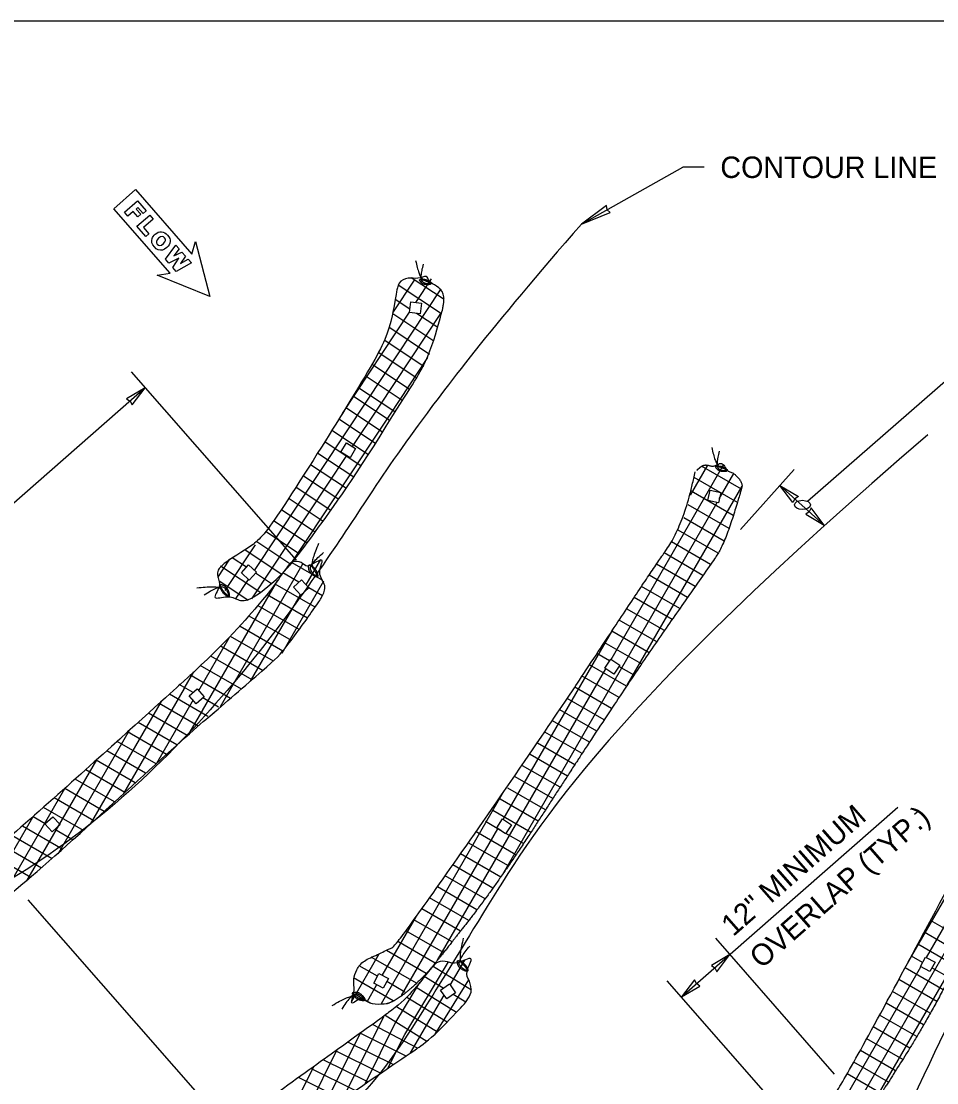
# Model space of a CAD drawing. Extents: x 99862 to 103680, y 99470 to 102076.
# Drawn here: x 100410 to 101092, y 101285 to 102076 of the extents above; entities that cross this region are included whole.
import ezdxf

# ---------------------------------------------------------------- set-up
doc = ezdxf.new("R2010")
doc.units = 0
for name, color, linetype in [('Level 1', 7, 'Continuous'), ('Level 10', 7, 'Continuous'), ('Level 15', 7, 'Continuous'), ('Level 20', 7, 'Continuous'), ('Level 4', 7, 'Continuous'), ('Level 9', 7, 'Continuous')]:
    doc.layers.add(name, color=color, linetype=linetype)

msp = doc.modelspace()

# ---------------------------------------------------------------- linework, layer by layer
at = {"layer": 'Level 1'}
msp.add_lwpolyline([(99862, 99999.5), (103151, 99999.5), (103151, 102075.5), (99862, 102075.5)], close=True, dxfattribs=at)
at = {"layer": 'Level 10'}
for p, q in [((100686.69, 101781.75), (100686.69, 101781.75)), ((100528.6, 101581.63), (100528.6, 101581.63)), ((100550.56, 101557.94), (100550.6, 101557.88)), ((100550.6, 101557.88), (100553.54, 101560.47))]:
    msp.add_line(p, q, dxfattribs=at)
for points, degree in [([(100703.82, 101897.11), (100706.88, 101883.28), (100711.8, 101883.38), (100716.73, 101879.3), (100709.52, 101879.05), (100707.92, 101880.94)], 2), ([(100707.92, 101880.94), (100706.18, 101882.83), (100708.14, 101883.42), (100715.85, 101880.26), (100711.97, 101879.45), (100706.5, 101882.66), (100709.63, 101894.37)], 2), ([(100686.69, 101781.75), (100703.73, 101807.89), (100713.64, 101823.92), (100724, 101860.58), (100724.42, 101863.23), (100725.56, 101872.86), (100719.55, 101878.66), (100713.08, 101881.07), (100712.79, 101887.05), (100705.43, 101882.88), (100698.53, 101885.09), (100692.9, 101882.35), (100691.65, 101880.34)], 3), ([(100691.65, 101880.34), (100690.4, 101878.32), (100689.61, 101874.46), (100683.89, 101838.84), (100667.45, 101813.31), (100649.17, 101783.11)], 3), ([(100649.17, 101783.11), (100643.46, 101773.88), (100595.75, 101697.56), (100583.93, 101685.4), (100556.89, 101669.91), (100555.08, 101662.87), (100559.51, 101654.84), (100550.53, 101643.35), (100564.54, 101648.13), (100570.49, 101644.09), (100580.38, 101642.5), (100606.82, 101665.1), (100621.99, 101685.13), (100660.69, 101738.67), (100686.69, 101781.75)], 3), ([(100924.56, 101757.81), (100927.68, 101743.99), (100932.6, 101744.13), (100937.55, 101740.07), (100930.34, 101739.78), (100928.74, 101741.66)], 2), ([(100928.74, 101741.66), (100926.99, 101743.55), (100928.95, 101744.14), (100936.66, 101741.02), (100932.79, 101740.19), (100927.31, 101743.38), (100930.37, 101755.1)], 2), ([(100913.39, 101740.65), (100915.97, 101743.47), (100919.92, 101745.31), (100926.13, 101743.35), (100932.33, 101747.32), (100936.21, 101739.99), (100941.25, 101738.92), (100948.01, 101730.88), (100945.85, 101724.48), (100945.34, 101721.84), (100933.71, 101685.57), (100922.62, 101668.96), (100878.53, 101606.33), (100829.81, 101533.12), (100767.38, 101436.3), (100724.87, 101381.61), (100709.01, 101362.12), (100686.58, 101343.34), (100671.98, 101342.39), (100662.3, 101348.01), (100654.75, 101341.78), (100658.72, 101354.02), (100656.73, 101360.34), (100662.32, 101375.12), (100684.12, 101383.21), (100693.17, 101391.91), (100793.37, 101535.2), (100878.11, 101663.54), (100904.5, 101701.51), (100912.19, 101739.82)], 2), ([(100631.4, 101686.31), (100624.74, 101670.67), (100629.62, 101667.34), (100631.58, 101659.91), (100624.37, 101664.7), (100624.13, 101667.65)], 2), ([(100624.13, 101667.65), (100623.75, 101670.72), (100626.07, 101669.92), (100631.39, 101661.46), (100627.04, 101663.38), (100623.94, 101670.32), (100635.16, 101679.58)], 2), ([(100611.16, 101672.08), (100609.65, 101671.07), (100605.18, 101665.16), (100592.45, 101646.1), (100558.31, 101608.42), (100528.6, 101581.63)], 3), ([(100550.6, 101557.88), (100559.43, 101565.55), (100597.07, 101597.71), (100605.65, 101606.27), (100632.18, 101643.31), (100633.34, 101645.74), (100638.42, 101655.09), (100629.46, 101663.66), (100637.37, 101677.27), (100625.16, 101669.8), (100622.44, 101668.85), (100617.18, 101673.65), (100612.67, 101673.09), (100611.16, 101672.08)], 3), ([(101201.98, 101650.48), (101204.23, 101654.65), (101209.68, 101657.73), (101216.7, 101655.95), (101223.8, 101660.57), (101224.45, 101654.62), (101231.06, 101652.6), (101237.42, 101647.19), (101236.87, 101637.51), (101236.61, 101634.83), (101228.53, 101597.61), (101219.1, 101580.01), (101181.24, 101513.43), (101139.8, 101435.86), (101086.99, 101333.49), (101049.94, 101274.95), (101036.04, 101254.03), (101011.04, 101229.85), (101001.08, 101230.82), (100994.88, 101234.48), (100983.57, 101230.11), (100989.45, 101240.88), (100984.53, 101248.61), (100985.9, 101255.76), (101011.94, 101272.88), (101018.02, 101275.83), (101103.33, 101434.43), (101175.32, 101570.33), (101197.92, 101610.67), (101201.44, 101646.58)], 2), ([(100528.6, 101581.63), (100528.11, 101581.18), (100470.66, 101529.07), (100345.88, 101417.9), (100320.67, 101410.22), (100299.49, 101400.95), (100293.76, 101394.13), (100297.49, 101385.18), (100287.56, 101376.44), (100301.23, 101377.9), (100305.39, 101373.25), (100317.46, 101371.44), (100346.05, 101382.29), (100366.25, 101397.24), (100420.98, 101439.69), (100505.45, 101518.02), (100543.69, 101552.46), (100550.6, 101557.88)], 3), ([(100720.66, 101374.47), (100718.94, 101373.7), (100717, 101372.6), (100697.09, 101346.06), (100683.68, 101336.84)], 3), ([(100704.56, 101309.85), (100704.78, 101309.98), (100713.59, 101315.17), (100739.82, 101342.78), (100741.44, 101344.93), (100746.22, 101351.69), (100744.31, 101360.85), (100739.79, 101366.11), (100749.24, 101380.94), (100733.21, 101371.83), (100728.29, 101375.07), (100722.37, 101375.24), (100720.66, 101374.47)], 3), ([(100683.65, 101336.86), (100679.43, 101333.35), (100655.62, 101316.88), (100531.24, 101226.43), (100387.02, 101132.84), (100378.6, 101128.6), (100349.84, 101116.39), (100347.55, 101104.92), (100340.78, 101099.98), (100337.73, 101096.69), (100347.02, 101095.39), (100349.87, 101092.19), (100366.06, 101083.31), (100391.52, 101093.94), (100413.21, 101106.63), (100472.21, 101142.93), (100564.63, 101211.69), (100635.94, 101263.16), (100694, 101302.8), (100704.56, 101309.85)], 3)]:
    msp.add_open_spline(points, degree=degree, dxfattribs=at)
at = {"layer": 'Level 15'}
for p, q in [((100827.57, 101924.36), (100903, 101966.69)), ((100919, 101966.69), (100903, 101966.69)), ((100995.89, 101717.8), (101136.22, 101840.29)), ((100491.66, 101814.31), (100614.68, 101673.96)), ((100502.21, 101802.28), (100177.84, 101517.98)), ((100946.01, 101696.71), (100986.06, 101741.52)), ((101008.42, 101700.01), (100975.37, 101729.56)), ((100901.95, 101348.47), (101063.39, 101489.97)), ((101075.63, 101484.69), (101077.71, 101486.32)), ((101016.17, 101290.98), (100927.5, 101392.14)), ((100987.79, 101250.53), (100891.4, 101360.5))]:
    msp.add_line(p, q, dxfattribs=at)
for points in [[(100827.57, 101924.36), (100848.94, 101932.93), (100846.56, 101935.02), (100846.02, 101938.14)], [(100502.21, 101802.28), (100488.37, 101794.2), (100490.96, 101792.37), (100492.45, 101789.57)], [(100975.37, 101729.56), (100989.15, 101721.38), (100986.55, 101719.57), (100985.04, 101716.78)], [(101008.42, 101700.01), (100998.76, 101712.79), (100997.24, 101710.01), (100994.65, 101708.19)], [(100938.06, 101380.05), (100924.29, 101371.85), (100926.89, 101370.04), (100928.4, 101367.26)], [(100901.95, 101348.47), (100915.79, 101356.55), (100913.21, 101358.38), (100911.71, 101361.18)]]:
    msp.add_lwpolyline(points, close=True, dxfattribs=at)
msp.add_ellipse((100992.2, 101715.06), major_axis=(-6, 0), ratio=0.57735, dxfattribs=at)
at = {"layer": 'Level 20'}
msp.add_line((100414.74, 101420.89), (100555.73, 101260.03), dxfattribs=at)
for points in [[(100550.26, 101870.27), (100511.05, 101886.39), (100520.73, 101887.65), (100478.73, 101935.81), (100495.06, 101950.06), (100537.06, 101901.89), (100539.63, 101911.32), (100550.26, 101870.27)], [(100550.26, 101870.27), (100511.05, 101886.39), (100520.73, 101887.65), (100478.73, 101935.81), (100495.06, 101950.06), (100537.06, 101901.89), (100539.63, 101911.32), (100550.26, 101870.27)], [(100496.38, 101941.58), (100502.83, 101934.18), (100500.61, 101932.25), (100496.74, 101936.68), (100495.44, 101935.55), (100498.83, 101931.67), (100496.61, 101929.74), (100493.23, 101933.62), (100489.34, 101930.23), (100486.77, 101933.19), (100496.38, 101941.58)], [(100496.38, 101941.58), (100502.83, 101934.18), (100500.61, 101932.25), (100496.74, 101936.68), (100495.44, 101935.55), (100498.83, 101931.67), (100496.61, 101929.74), (100493.23, 101933.62), (100489.34, 101930.23), (100486.77, 101933.19), (100496.38, 101941.58)], [(100505.54, 101931.07), (100508.12, 101928.11), (100500.91, 101921.82), (100504.95, 101917.2), (100502.54, 101915.1), (100495.93, 101922.68), (100505.54, 101931.07)], [(100505.54, 101931.07), (100508.12, 101928.11), (100500.91, 101921.82), (100504.95, 101917.2), (100502.54, 101915.1), (100495.93, 101922.68), (100505.54, 101931.07)], [(100518.91, 101916.11), (100519.82, 101914.91), (100520.45, 101913.7), (100520.79, 101912.49), (100520.85, 101911.28), (100520.63, 101910.09), (100520.15, 101908.94), (100519.39, 101907.85), (100518.36, 101906.81), (100516.69, 101905.61), (100515.09, 101904.96), (100513.52, 101904.81), (100511.97, 101905.13), (100510.47, 101905.95), (100509.03, 101907.29), (100507.86, 101908.89), (100507.2, 101910.44), (100507.02, 101911.99), (100507.34, 101913.6), (100507.68, 101914.42), (100508.17, 101915.21), (100508.8, 101915.98), (100509.58, 101916.73), (100510.76, 101917.62), (100511.96, 101918.23), (100513.17, 101918.57), (100514.4, 101918.62), (100515.6, 101918.41), (100516.76, 101917.91), (100517.86, 101917.15), (100518.91, 101916.11)], [(100518.91, 101916.11), (100519.82, 101914.91), (100520.45, 101913.7), (100520.79, 101912.49), (100520.85, 101911.28), (100520.63, 101910.09), (100520.15, 101908.94), (100519.39, 101907.85), (100518.36, 101906.81), (100516.69, 101905.61), (100515.09, 101904.96), (100513.52, 101904.81), (100511.97, 101905.13), (100510.47, 101905.95), (100509.03, 101907.29), (100507.86, 101908.89), (100507.2, 101910.44), (100507.02, 101911.99), (100507.34, 101913.6), (100507.68, 101914.42), (100508.17, 101915.21), (100508.8, 101915.98), (100509.58, 101916.73), (100510.76, 101917.62), (100511.96, 101918.23), (100513.17, 101918.57), (100514.4, 101918.62), (100515.6, 101918.41), (100516.76, 101917.91), (100517.86, 101917.15), (100518.91, 101916.11)], [(100517.27, 101913.2), (100516.69, 101914.18), (100515.81, 101914.86), (100514.77, 101915.08), (100513.55, 101914.74), (100512.16, 101913.77), (100511, 101912.53), (100510.51, 101911.37), (100510.59, 101910.3), (100511.17, 101909.32), (100512.07, 101908.6), (100513.1, 101908.37), (100514.33, 101908.74), (100515.84, 101909.82), (100516.91, 101911), (100517.36, 101912.13), (100517.27, 101913.2)], [(100517.27, 101913.2), (100516.69, 101914.18), (100515.81, 101914.86), (100514.77, 101915.08), (100513.55, 101914.74), (100512.16, 101913.77), (100511, 101912.53), (100510.51, 101911.37), (100510.59, 101910.3), (100511.17, 101909.32), (100512.07, 101908.6), (100513.1, 101908.37), (100514.33, 101908.74), (100515.84, 101909.82), (100516.91, 101911), (100517.36, 101912.13), (100517.27, 101913.2)], [(100534.3, 101898.1), (100536.68, 101895.37), (100525.3, 101889.01), (100522.75, 101891.93), (100527.32, 101898.9), (100519.8, 101895.31), (100517.26, 101898.23), (100525, 101908.76), (100527.47, 101905.92), (100523.58, 101900.63), (100529.58, 101903.5), (100532.18, 101900.52), (100528.53, 101894.95), (100534.3, 101898.1)], [(100534.3, 101898.1), (100536.68, 101895.37), (100525.3, 101889.01), (100522.75, 101891.93), (100527.32, 101898.9), (100519.8, 101895.31), (100517.26, 101898.23), (100525, 101908.76), (100527.47, 101905.92), (100523.58, 101900.63), (100529.58, 101903.5), (100532.18, 101900.52), (100528.53, 101894.95), (100534.3, 101898.1)]]:
    msp.add_lwpolyline(points, dxfattribs=at)
at = {"layer": 'Level 4'}
for points in [[(100699.28, 101858.39), (100700.2, 101866.33), (100708.15, 101865.41), (100707.23, 101857.47)], [(100648.1, 101754.49), (100652.3, 101761.3), (100659.1, 101757.1), (100654.91, 101750.29)], [(100921.72, 101718.27), (100923.41, 101726.09), (100931.23, 101724.41), (100929.54, 101716.59)], [(100573.87, 101664.49), (100579.3, 101670.36), (100585.17, 101664.93), (100579.74, 101659.06)], [(100612.85, 101653.87), (100618.8, 101659.22), (100624.15, 101653.27), (100618.21, 101647.92)], [(100844.84, 101593.44), (100849.27, 101600.1), (100855.93, 101595.66), (100851.5, 101589)], [(100534.96, 101572.73), (100540.91, 101578.08), (100546.26, 101572.14), (100540.31, 101566.79)], [(100427.4, 101477.43), (100433.34, 101482.78), (100438.69, 101476.83), (100432.75, 101471.48)], [(100764.24, 101474.45), (100768.68, 101481.11), (100775.34, 101476.68), (100770.9, 101470.02)], [(101080.19, 101371.16), (101083.96, 101378.21), (101091.02, 101374.44), (101087.25, 101367.38)], [(100672.67, 101358.84), (100676.48, 101365.88), (100683.52, 101362.08), (100679.71, 101355.04)], [(100722.47, 101353.58), (100729.02, 101358.17), (100733.61, 101351.61), (100727.05, 101347.03)]]:
    msp.add_lwpolyline(points, close=True, dxfattribs=at)
for points, degree in [([(100827.57, 101924.36), (100760.06, 101847.66), (100689.54, 101753.7), (100669.26, 101721.45), (100565.8, 101567.25), (100397.3, 101413.08), (100195.24, 101363.06), (100041.72, 101315.14), (99995.15, 101304.04), (99966.8, 101295.66)], 3), ([(101085.75, 101767.26), (100851.58, 101567.5), (100738.84, 101387.48), (100680.23, 101288.16), (100628.41, 101241.49), (100408.17, 101099.51), (100270.3, 101083.42), (100093.57, 101042.42), (100035.51, 101028.27), (100002.7, 101021.57)], 3), ([(100540.79, 101653.3), (100557.68, 101655.2), (100559.47, 101649.57), (100566.02, 101645.56), (100563.5, 101653.85), (100560.74, 101654.92)], 2), ([(100560.74, 101654.92), (100557.91, 101656.16), (100558.01, 101653.71), (100564.59, 101646.19), (100564, 101650.91), (100558.23, 101655.87), (100546.15, 101647.77)], 2), ([(101340.36, 101649.79), (101258.99, 101563.81), (101150.87, 101434.31), (101122.52, 101374.36), (101074.07, 101271.74)], 3), ([(100739.35, 101392.36), (100735.36, 101375.84), (100740.73, 101373.36), (100743.88, 101366.36), (100735.98, 101369.89), (100735.26, 101372.76)], 2), ([(100735.26, 101372.76), (100734.38, 101375.73), (100736.8, 101375.32), (100743.44, 101367.86), (100738.83, 101369.03), (100734.63, 101375.37), (100744.17, 101386.35)], 2), ([(100641.6, 101342.14), (100656.23, 101350.81), (100660.17, 101346.4), (100667.79, 101345.44), (100662.09, 101351.96), (100659.13, 101351.81)], 2), ([(100659.13, 101351.81), (100656.04, 101351.78), (100657.14, 101349.58), (100666.22, 101345.42), (100663.75, 101349.49), (100656.46, 101351.64), (100648.76, 101339.3)], 2)]:
    msp.add_open_spline(points, degree=degree, dxfattribs=at)
at = {"layer": 'Level 9'}
for p, q in [((100686.93, 101858.18), (100703.07, 101882.52)), ((100725, 101868.12), (100700.52, 101884.34)), ((100704.04, 101865.89), (100715.66, 101883.43)), ((100667.9, 101793.24), (100722.84, 101876.15)), ((100723.05, 101857.42), (100690.81, 101878.78)), ((100699.58, 101860.97), (100688.63, 101868.23)), ((100649.18, 101783.1), (100699.32, 101858.77)), ((100676.43, 101788.02), (100722.69, 101857.83)), ((100717.34, 101837.21), (100686.87, 101857.4)), ((100720.24, 101847.28), (100704.38, 101857.8)), ((100714.24, 101827.26), (100684.52, 101846.96)), ((100709.93, 101818.13), (100681, 101837.3)), ((100704.71, 101809.59), (100676.6, 101828.22)), ((100699.3, 101801.18), (100671.5, 101819.6)), ((100684.96, 101782.79), (100712.95, 101825.03)), ((100693.87, 101792.78), (100666.13, 101811.16)), ((100688.41, 101784.4), (100660.81, 101802.69)), ((100649.17, 101783.11), (100659.36, 101798.48)), ((100684.39, 101777.95), (100657.15, 101796)), ((100583.74, 101666.26), (100667.89, 101793.26)), ((100679.17, 101769.41), (100651.88, 101787.49)), ((100656.85, 101758.49), (100676.42, 101788.03)), ((100610.12, 101669.87), (100684.96, 101782.81)), ((100673.91, 101760.9), (100646.62, 101778.99)), ((100668.58, 101752.43), (100641.35, 101770.48)), ((100663.19, 101744.01), (100636.07, 101761.98)), ((100581.72, 101645.12), (100652.43, 101751.82)), ((100657.72, 101735.64), (100630.79, 101753.48)), ((100652.16, 101727.33), (100625.5, 101745)), ((100849.52, 101599.94), (100933.3, 101745.06)), ((100908.7, 101722.45), (100921.55, 101744.7)), ((100946.65, 101726.83), (100917.04, 101743.93)), ((100930.22, 101719.71), (100941, 101738.39)), ((100646.48, 101719.1), (100620.19, 101736.52)), ((100943.74, 101716.97), (100911.48, 101735.59)), ((100640.66, 101710.96), (100614.86, 101728.05)), ((100861.53, 101580.75), (100947.19, 101729.11)), ((100940.64, 101707.21), (100909.29, 101725.31)), ((100634.78, 101702.85), (100609.5, 101719.61)), ((100768.45, 101439.53), (100928.54, 101716.8)), ((100937.44, 101697.51), (100907.02, 101715.07)), ((100628.9, 101694.76), (100604.11, 101711.18)), ((100622.99, 101686.68), (100598.66, 101702.8)), ((100933.8, 101688.07), (100903.78, 101705.4)), ((100617.04, 101678.62), (100592.55, 101694.85)), ((100929.32, 101679.1), (100899.61, 101696.26)), ((100561.82, 101651.29), (100584.45, 101685.44)), ((100610.86, 101670.72), (100585.34, 101687.63)), ((100923.75, 101670.78), (100894.65, 101687.58)), ((100577.74, 101668.68), (100567.11, 101675.72)), ((100603.95, 101663.3), (100576.81, 101681.29)), ((100918.03, 101662.53), (100889.05, 101679.26)), ((100556.3, 101661.06), (100565.25, 101674.57)), ((100588.42, 101649.6), (100558.34, 101669.54)), ((100558.37, 101564.81), (100619.75, 101671.13)), ((100634.52, 101658.79), (100611.79, 101671.91)), ((100622.22, 101655.42), (100633.13, 101674.31)), ((100912.28, 101654.3), (100883.4, 101670.97)), ((100569.61, 101644.95), (100579.26, 101659.5)), ((100596.45, 101656.28), (100584.5, 101664.2)), ((100616.84, 101657.45), (100604.77, 101664.41)), ((100906.51, 101646.09), (100877.8, 101662.66)), ((100544.97, 101561.81), (100601.05, 101658.95)), ((100579, 101643.85), (100557.78, 101657.91)), ((100628.95, 101638.91), (100599.14, 101656.12)), ((100604.25, 101604.52), (100635.41, 101658.49)), ((100634.25, 101647.4), (100624.12, 101653.24)), ((100900.74, 101637.87), (100872.22, 101654.34)), ((100580.8, 101583.67), (100618.02, 101648.13)), ((100623.25, 101630.65), (100593.16, 101648.02)), ((100894.97, 101629.65), (100866.65, 101646)), ((100617.02, 101622.15), (100586.39, 101639.83)), ((100889.24, 101621.42), (100861.1, 101637.66)), ((100611.18, 101613.97), (100579.71, 101632.14)), ((100883.54, 101613.16), (100855.56, 101629.32)), ((101071.04, 101374.42), (101218.76, 101630.28)), ((100604.91, 101606.05), (100572.9, 101624.53)), ((100769.17, 101480.78), (100850.73, 101622.04)), ((100877.87, 101604.89), (100850.02, 101620.97)), ((100542.07, 101576.79), (100564.79, 101616.16)), ((100597.87, 101598.56), (100565.89, 101617.03)), ((100872.22, 101596.6), (100844.49, 101612.61)), ((101012.22, 101232.54), (101231.83, 101612.92)), ((100590.24, 101591.42), (100558.9, 101609.51)), ((100848.41, 101598.8), (100838.96, 101604.25)), ((100581.91, 101584.68), (100551.09, 101602.48)), ((100861.02, 101579.98), (100833.44, 101595.9)), ((100531.32, 101578.18), (100538.56, 101590.71)), ((100565.81, 101570.88), (100535.45, 101588.41)), ((100573.89, 101577.77), (100543.28, 101595.44)), ((100720.12, 101375.81), (100845.51, 101592.99)), ((100866.61, 101588.29), (100855.35, 101594.79)), ((100537.95, 101575.42), (100527.63, 101581.38)), ((100855.45, 101571.64), (100827.92, 101587.54)), ((100486.28, 101500.17), (100531.4, 101578.32)), ((100548.97, 101557.54), (100520.29, 101574.1)), ((100849.9, 101563.3), (100822.39, 101579.18)), ((100461.52, 101477.28), (100514.27, 101568.64)), ((100510.83, 101522.68), (100538.26, 101570.2)), ((100541.38, 101550.38), (100512.51, 101567.05)), ((100556.87, 101564.5), (100545.24, 101571.22)), ((100844.37, 101554.94), (100816.86, 101570.83)), ((100533.57, 101543.34), (100504.71, 101560)), ((100535.09, 101544.71), (100545.12, 101562.09)), ((100838.86, 101546.58), (100811.32, 101562.48)), ((100525.78, 101536.29), (100496.91, 101552.95)), ((100833.36, 101538.21), (100805.78, 101554.13)), ((100437.22, 101455.19), (100490.13, 101546.83)), ((100518.01, 101529.23), (100489.11, 101545.91)), ((100827.87, 101529.83), (100800.24, 101545.78)), ((100510.25, 101522.16), (100481.3, 101538.88)), ((100822.4, 101521.44), (100794.69, 101537.44)), ((100414.05, 101435.06), (100466.1, 101525.21)), ((100494.79, 101507.99), (100465.66, 101524.81)), ((100502.52, 101515.08), (100473.48, 101531.84)), ((100816.94, 101513.05), (100789.14, 101529.1)), ((100487.08, 101500.9), (100457.83, 101517.79)), ((100811.49, 101504.65), (100783.59, 101520.75)), ((100479.37, 101493.8), (100450, 101510.76)), ((100806.04, 101496.24), (100778.03, 101512.42)), ((100392.36, 101417.49), (100442.15, 101503.74)), ((100471.68, 101486.69), (100442.16, 101503.74)), ((100678.45, 101343.64), (100769.44, 101501.23)), ((100800.61, 101487.83), (100772.47, 101504.08)), ((100464, 101479.58), (100434.31, 101496.72)), ((100795.18, 101479.42), (100766.91, 101495.74)), ((101084.58, 101377.88), (101154.52, 101499.01)), ((100456.31, 101472.48), (100426.46, 101489.71)), ((100789.7, 101471.04), (100761.35, 101487.41)), ((100371.53, 101401.42), (100418.3, 101482.42)), ((100427.53, 101477.55), (100418.61, 101482.7)), ((100767.2, 101472.48), (100755.78, 101479.08)), ((100440.76, 101458.36), (100410.75, 101475.69)), ((100448.57, 101465.4), (100434.81, 101473.34)), ((100693.33, 101349.41), (100765.17, 101473.84)), ((100778.6, 101454.35), (100748.84, 101471.54)), ((100784.18, 101462.68), (100771.06, 101470.25)), ((100424.95, 101444.39), (100394.97, 101461.7)), ((100432.9, 101451.35), (100402.88, 101468.68)), ((100772.96, 101446.06), (100743.09, 101463.31)), ((100416.91, 101437.49), (100387.03, 101454.74)), ((100767.25, 101437.81), (100737.34, 101455.08)), ((100761.46, 101429.61), (100731.57, 101446.86)), ((100755.56, 101421.47), (100725.8, 101438.65)), ((100749.54, 101413.4), (100720.01, 101430.44)), ((100743.37, 101405.41), (100714.21, 101422.25)), ((100737.16, 101397.45), (100708.38, 101414.06)), ((101039.04, 101258.99), (101129.09, 101414.96)), ((100678.97, 101364.54), (100704.16, 101408.17)), ((100730.94, 101389.5), (100702.52, 101405.9)), ((101115.74, 101389.21), (101087.66, 101405.42)), ((100724.69, 101381.56), (100696.6, 101397.77)), ((101111.14, 101380.31), (101082.94, 101396.6)), ((100711.57, 101366.04), (100682.09, 101383.06)), ((100718.38, 101373.65), (100690.52, 101389.74)), ((101106.51, 101371.44), (101078.21, 101387.78)), ((100656.06, 101344.85), (100676.72, 101380.64)), ((100704.33, 101358.67), (100670.65, 101378.11)), ((100695.79, 101320.4), (100728.27, 101374.65)), ((100729.63, 101357.29), (100740.56, 101375.78)), ((101081.8, 101374.16), (101073.48, 101378.96)), ((100675.37, 101363.84), (100661.79, 101371.68)), ((100745.53, 101353.53), (100716.45, 101371.5)), ((101012.87, 101253.67), (101080.58, 101370.95)), ((101097.1, 101353.78), (101068.75, 101370.15)), ((101101.83, 101362.6), (101088.73, 101370.16)), ((100686.94, 101345.61), (100657.53, 101362.6)), ((100695.76, 101352.07), (100682.3, 101359.84)), ((100689.11, 101329.56), (100707.04, 101359.32)), ((100724.32, 101354.88), (100710.26, 101363.58)), ((100718.47, 101320.75), (100743.53, 101361.29)), ((101092.31, 101345), (101064.01, 101361.34)), ((100670.29, 101343.68), (100658.39, 101350.55)), ((100667.64, 101344.92), (100674.97, 101357.61)), ((100734.28, 101336.97), (100704.18, 101355.57)), ((101087.44, 101336.26), (101059.27, 101352.53)), ((100727.26, 101329.56), (100697.36, 101348.03)), ((100699.88, 101306.92), (100725.16, 101349.72)), ((100741.11, 101344.51), (100731.73, 101350.3)), ((101082.5, 101327.57), (101054.52, 101343.72)), ((100720.05, 101322.25), (100689.51, 101341.13)), ((101077.46, 101318.93), (101049.76, 101334.92)), ((100649.19, 101272.1), (100680.03, 101333.97)), ((100666.21, 101283.83), (100689.12, 101329.79)), ((100705.18, 101310.22), (100671.68, 101327.98)), ((100712.28, 101315.3), (100681.01, 101334.63)), ((100632.03, 101260.09), (100662.72, 101321.67)), ((100696.36, 101304.51), (100662.4, 101321.44)), ((100683.16, 101295.42), (100695.8, 101320.41)), ((101072.29, 101310.37), (101044.98, 101326.13)), ((100686.95, 101298.02), (100653.18, 101314.86)), ((101066.99, 101301.88), (101040.18, 101317.36)), ((100614.74, 101247.81), (100645.37, 101309.25)), ((100677.52, 101291.55), (100643.99, 101308.27)), ((101061.63, 101293.43), (101035.36, 101308.6)), ((100611.77, 101264.27), (100627.92, 101296.68)), ((100668.06, 101285.09), (100634.82, 101301.66)), ((101056.25, 101284.99), (101030.49, 101299.86)), ((100649.24, 101272.13), (100616.53, 101288.43)), ((100658.63, 101278.62), (100625.67, 101295.05)), ((101050.85, 101276.56), (101025.57, 101291.15))]:
    msp.add_line(p, q, dxfattribs=at)

# ---------------------------------------------------------------- texts
at = {"layer": 'Level 20'}
for s, rotation, p in [('CONTOUR LINE (TYP.)', 360, (100931, 101958.69)), ('12" MINIMUM ', 41.23358, (100940.5, 101392.94)), ('OVERLAP (TYP.)', 41.23358, (100961.59, 101368.88))]:
    msp.add_text(s, height=16, rotation=rotation, dxfattribs=at).set_placement(p)

doc.saveas('drawing.dxf')
